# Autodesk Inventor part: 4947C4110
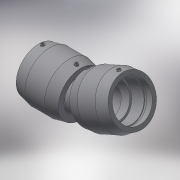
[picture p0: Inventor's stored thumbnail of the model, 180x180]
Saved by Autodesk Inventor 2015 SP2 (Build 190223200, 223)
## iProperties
Created: 2017-06
Part Number: 4947C4110
Material: Generic
Description: PLASSON ADJUSTABLE ELBOW 110
Document SubType Name: Modeling
Designer: KIM
Mass: 1954.62 g
Surface Area: 3006.06 cm^2
Volume: 1954.62 cm^3
Density: 1 g/cm^3
Appearance: Default
Author: KIM
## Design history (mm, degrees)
derived "4947C4.ipt"
feature "Solid1::4947C4.ipt"
tag "TaggingFeature1"
body "Solid1"
other parameters: "d0" = 144.8, "d5" = 126, "d8" = 168 deg, "d10" = 32, "d11" = 10.66667, "d29" = 83, "d30" = 15, "d31" = 57.92, "d34" = 5 deg, "d41" = 4, "d42" = 14, "d43" = 0, "d48" = 99, "d49" = 24 deg, "d50" = 362, "d51" = 78 deg, "d52" = 90 deg, "d55" = 32.4, "d57" = 168 deg, "d58" = 6.48, "d60" = 40.94964, "d62" = 3, "d63" = 0, "L_" = 362, "A_" = 83, "d_2" = 12, "L_0" = 148, "d54" = 64.8, "d59" = 136.4988
